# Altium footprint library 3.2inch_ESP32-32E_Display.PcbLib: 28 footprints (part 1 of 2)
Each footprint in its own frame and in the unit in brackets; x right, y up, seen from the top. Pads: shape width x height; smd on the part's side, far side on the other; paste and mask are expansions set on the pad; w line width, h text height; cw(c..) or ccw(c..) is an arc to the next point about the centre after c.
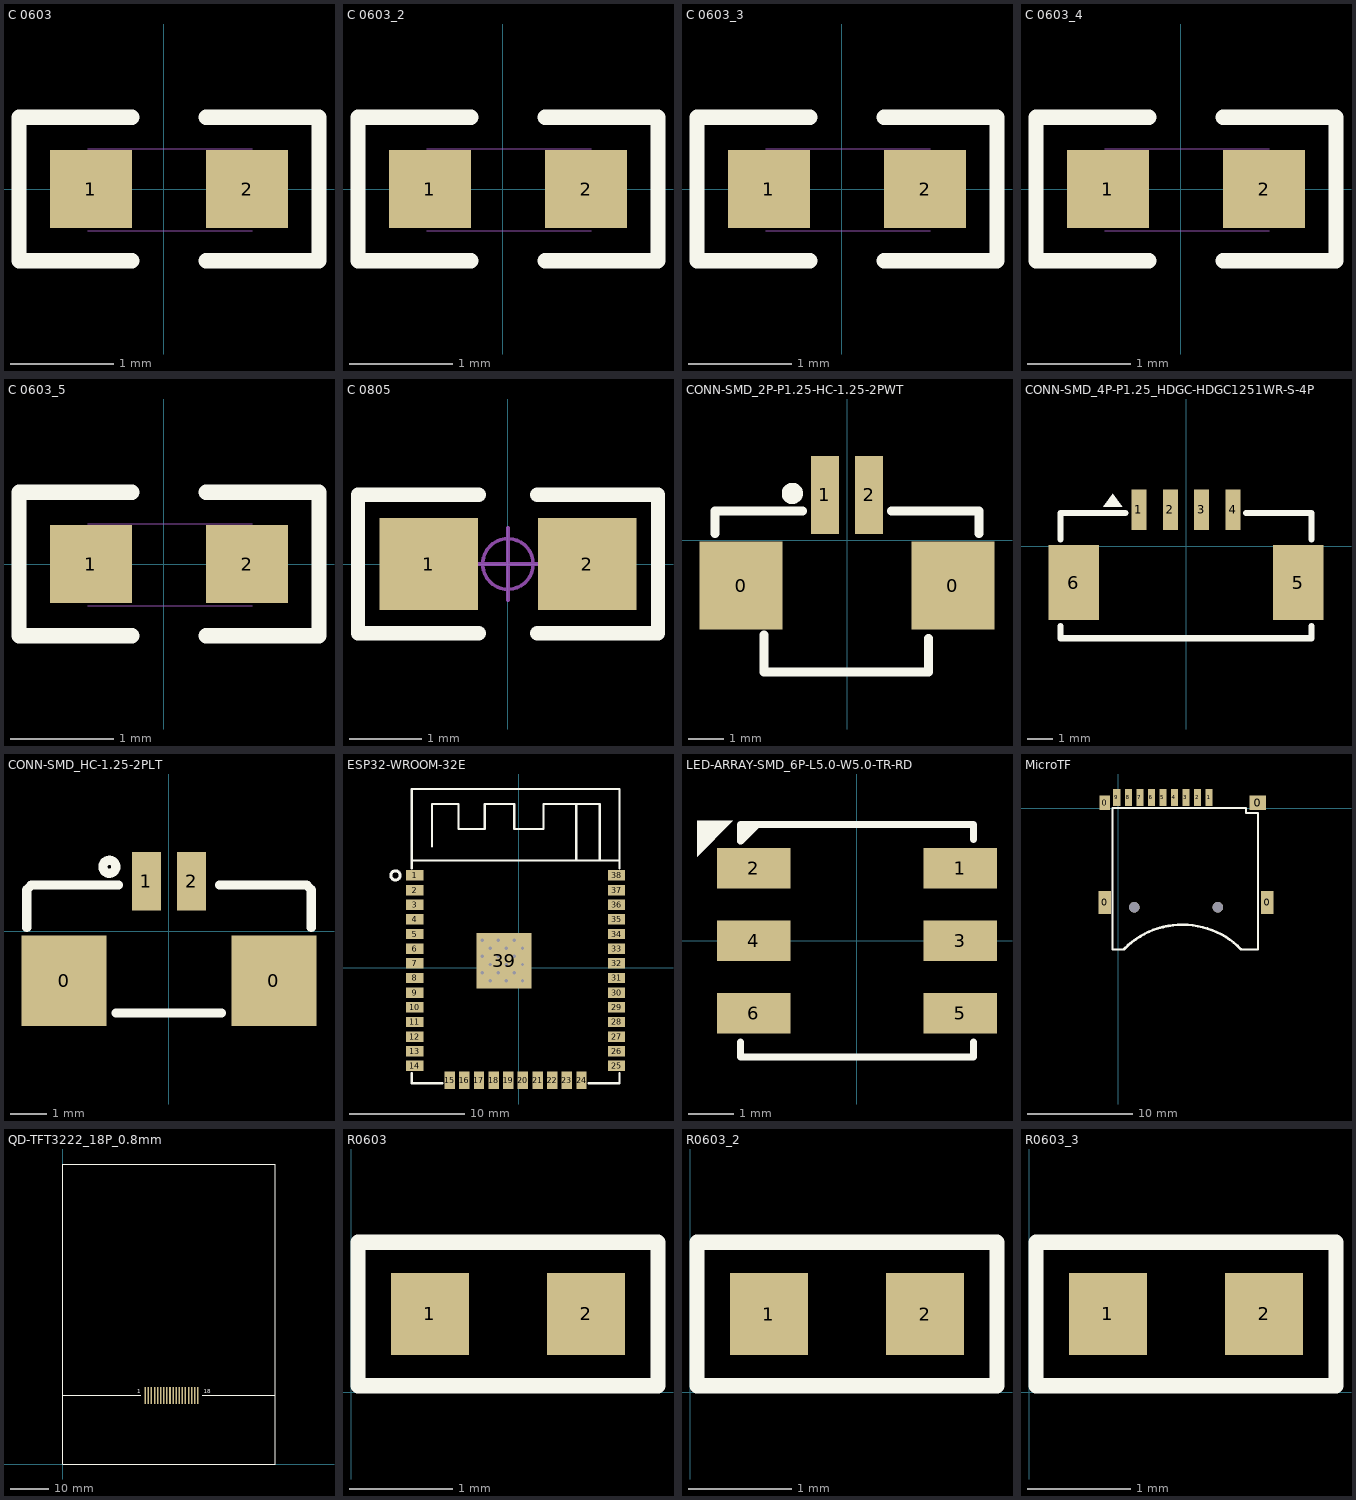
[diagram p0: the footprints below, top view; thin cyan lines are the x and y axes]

## C 0603 [mm] "无极性贴片电容"
pads (2):
  rect 0.8x0.76 smd: 1(-0.711,0) 2(0.809,0)
Top Overlay:
  lines w0.15: -0.311,-0.7 -1.411,-0.7 -1.411,0.7 -0.311,0.7 ; 0.409,-0.7 1.509,-0.7 1.509,0.7 0.409,0.7
Mechanical 13:
  lines w0.01: -0.742,-0.406 0.858,-0.406 ; -0.742,0.394 0.858,0.394
3D body "C 0603.STEP": height 0.81, standoff -0.01, extent -0.742,-0.41 0.858,0.41

## C 0603_2 [mm]
pads (2):
  rect 0.8x0.76 smd: 1(-0.711,0) 2(0.809,0)
Top Overlay:
  lines w0.15: -0.311,-0.7 -1.411,-0.7 -1.411,0.7 -0.311,0.7 ; 0.409,-0.7 1.509,-0.7 1.509,0.7 0.409,0.7
Mechanical 13:
  lines w0.01: -0.742,-0.406 0.858,-0.406 ; -0.742,0.394 0.858,0.394
3D body "C 0603.STEP": height 0.81, standoff -0.01, extent -0.742,-0.41 0.858,0.41

## C 0603_3 [mm]
pads (2):
  rect 0.8x0.76 smd: 1(-0.711,0) 2(0.809,0)
Top Overlay:
  lines w0.15: -0.311,-0.7 -1.411,-0.7 -1.411,0.7 -0.311,0.7 ; 0.409,-0.7 1.509,-0.7 1.509,0.7 0.409,0.7
Mechanical 13:
  lines w0.01: -0.742,-0.406 0.858,-0.406 ; -0.742,0.394 0.858,0.394
3D body "C 0603.STEP": height 0.81, standoff -0.01, extent -0.742,-0.41 0.858,0.41

## C 0603_4 [mm]
pads (2):
  rect 0.8x0.76 smd: 1(-0.711,0) 2(0.809,0)
Top Overlay:
  lines w0.15: -0.311,-0.7 -1.411,-0.7 -1.411,0.7 -0.311,0.7 ; 0.409,-0.7 1.509,-0.7 1.509,0.7 0.409,0.7
Mechanical 13:
  lines w0.01: -0.742,-0.406 0.858,-0.406 ; -0.742,0.394 0.858,0.394
3D body "C 0603.STEP": height 0.81, standoff -0.01, extent -0.742,-0.41 0.858,0.41

## C 0603_5 [mm]
pads (2):
  rect 0.8x0.76 smd: 1(-0.711,0) 2(0.809,0)
Top Overlay:
  lines w0.15: -0.311,-0.7 -1.411,-0.7 -1.411,0.7 -0.311,0.7 ; 0.409,-0.7 1.509,-0.7 1.509,0.7 0.409,0.7
Mechanical 13:
  lines w0.01: -0.742,-0.406 0.858,-0.406 ; -0.742,0.394 0.858,0.394
3D body "C 0603.STEP": height 0.81, standoff -0.01, extent -0.742,-0.41 0.858,0.41

## C 0805 [mm] "无极性贴片电容"
height 0.5
pads (2):
  rect 1.36x1.27 smd: 1(-1.094,0) 2(1.094,0)
Top Overlay:
  lines w0.2: -0.406,-0.955 -2.074,-0.955 -2.074,0.955 -0.406,0.955 ; 0.406,-0.955 2.074,-0.955 ; 0.406,0.955 2.074,0.955 ; 2.075,-0.955 2.075,0.955
Mechanical 15:
  circle w0.05: c0,0 r0.35
  lines w0.05: -0.5,0 0.5,0 ; 0,-0.5 0,0.5
3D body "C 0805.STEP": height 0.51, standoff -0.01, extent -1,-0.61 1,0.61

## CONN-SMD_2P-P1.25-HC-1.25-2PWT [mm]
pads (4):
  rect 2.35x2.5 smd paste+0 mask+0.05: 0(-3.005,-1.285) 0(3.005,-1.285)
  rect 0.8x2.2 smd paste+0 mask+0.05: 1(-0.625,1.285) 2(0.625,1.285)
Top Overlay:
  circle w0.3: c-1.55,1.33 r0.15
  lines w0.254: -3.75,0.196 -3.75,0.835 -1.256,0.835 ; -2.36,-2.69 -2.36,-3.73 2.31,-3.73 2.31,-2.78 ; 1.256,0.835 3.75,0.835 3.75,0.196

## CONN-SMD_4P-P1.25_HDGC-HDGC1251WR-S-4P [mm]
pads (6):
  rect 0.6x1.6 smd mask+0.05: 1(-1.875,1.45) 2(-0.625,1.45) 3(0.625,1.45) 4(1.875,1.45)
  rect 2x3 smd mask+0.05: 5(4.475,-1.45) 6(-4.475,-1.45)
Top Overlay:
  region: -3.175,1.577 -3.302,1.577 -2.921,2.085 -2.54,1.577 -3.175,1.577
  lines w0.254: -5,-3.181 -5,-3.669 5,-3.669 5,-3.181 ; -5,0.281 -5,1.323 -2.413,1.323 ; 2.406,1.323 5,1.323 5,0.281

## CONN-SMD_HC-1.25-2PLT [mm]
pads (4):
  rect 2.35x2.5 smd paste+0 mask+0.05: 0(-2.9,-1.38) 0(2.9,-1.38)
  rect 0.8x1.62 smd paste+0 mask+0.05: 1(-0.625,1.38) 2(0.625,1.38)
Top Overlay:
  circle w0.254: c-1.651,1.778 r0.18
  lines w0.254: -3.937,0.101 -3.937,1.143 -3.81,1.27 -1.397,1.27 ; -1.47,-2.27 1.451,-2.27 ; 1.397,1.27 3.81,1.27 3.937,1.143 3.937,0.101

## ESP32-WROOM-32E [mm]
pads (39):
  rect 1.5x0.9 smd mask+0.051: 1(-9.004,7.987) 2(-9.004,6.717) 3(-9.004,5.447) 4(-9.004,4.177) 5(-9.004,2.907) 6(-9.004,1.637) 7(-9.004,0.367) 8(-9.004,-0.903) 9(-9.004,-2.173) 10(-9.004,-3.443) 11(-9.004,-4.713) 12(-9.004,-5.983) 13(-9.004,-7.253) 14(-9.004,-8.523) 25(8.496,-8.523) 26(8.496,-7.253) 27(8.496,-5.983) 28(8.496,-4.713) 29(8.496,-3.443) 30(8.496,-2.173) 31(8.496,-0.903) 32(8.496,0.367) 33(8.496,1.637) 34(8.496,2.907) 35(8.496,4.177) 36(8.496,5.447) 37(8.496,6.717) 38(8.496,7.987)
  rect 0.9x1.5 smd mask+0.051: 15(-5.969,-9.774) 16(-4.699,-9.774) 17(-3.429,-9.774) 18(-2.159,-9.774) 19(-0.889,-9.774) 20(0.381,-9.774) 21(1.651,-9.774) 22(2.921,-9.774) 23(4.191,-9.774) 24(5.461,-9.774)
  rect 4.8x4.8 smd mask+0.051: 39(-1.254,0.576)
via -1.054,-1.133 diameter 0.5 hole 0.3
via -2.454,-1.133 diameter 0.5 hole 0.3
via -2.454,0.267 diameter 0.5 hole 0.3
via -1.054,0.267 diameter 0.5 hole 0.3
via -1.054,1.667 diameter 0.5 hole 0.3
via -0.354,0.967 diameter 0.5 hole 0.3
via -0.354,-0.433 diameter 0.5 hole 0.3
via -3.154,-0.433 diameter 0.5 hole 0.3
via -3.154,0.967 diameter 0.5 hole 0.3
via -2.454,1.667 diameter 0.5 hole 0.3
via -1.754,-0.433 diameter 0.5 hole 0.3
via -1.754,0.967 diameter 0.5 hole 0.3
via -1.754,2.367 diameter 0.5 hole 0.3
via -0.354,2.367 diameter 0.5 hole 0.3
via 0.346,1.667 diameter 0.5 hole 0.3
via 0.346,0.267 diameter 0.5 hole 0.3
via -3.154,2.367 diameter 0.5 hole 0.3
via 0.346,-1.133 diameter 0.5 hole 0.3
Top Overlay:
  circle w0.254: c-10.668,7.986 r0.402
  lines w0.203: -9.254,-9.15 -9.254,-10.023 -6.596,-10.023 ; -9.254,8.613 -9.254,15.476 8.746,15.477 8.746,8.614 ; -9.254,9.287 8.746,9.287 ; -7.493,10.489 -7.493,14.172 -5.207,14.172 -5.207,12.013 -2.921,12.013 -2.921,14.172 -0.381,14.172 -0.381,12.013 2.159,12.013 2.159,14.172 5.011,14.172 5.011,9.287 ; 4.808,14.172 7.043,14.172 7.043,9.287 ; 6.088,-10.023 8.746,-10.023 8.746,-9.15
3D body "ESP32-WROOM-32E_20210903.STEP": height 3.2, standoff 0.1, extent -9.254,-10.023 8.746,15.477

## LED-ARRAY-SMD_6P-L5.0-W5.0-TR-RD [mm]
pads (6):
  rect 1.625x0.896 smd mask+0.051: 1(2.288,1.6) 2(-2.288,1.6) 3(2.288,0) 4(-2.288,0) 5(2.288,-1.6) 6(-2.288,-1.6)
Top Overlay:
  region: -2.874,2.652 -3.54,2.652 -3.54,1.859 -2.747,2.652
  region: -2.54,2.159 -2.54,2.202 -2.576,2.239
  region: -2.286,2.576 -2.576,2.576 -2.576,2.239 -2.497,2.239 -2.159,2.576
  lines w0.152: -2.576,-2.239 -2.576,-2.576 2.576,-2.576 2.576,-2.239 ; -2.202,2.576 -2.576,2.202 -2.576,2.576 2.576,2.576 2.576,2.239

## MicroTF [mm]
height 2.65
pads (15):
  rect 1x1.4 smd: 0(-1.3,0.526)
  rect 1.2x2.2 smd: 0(-1.3,-8.994) 0(14.2,-8.994)
  rect 1.6x1.4 smd: 0(13.3,0.526)
  rect 0.7x1.6 smd: 1(8.65,1.026) 2(7.55,1.026) 3(6.45,1.026) 4(5.35,1.026) 5(4.25,1.026) 6(3.15,1.026) 7(2.05,1.026) 8(0.95,1.026) 9(-0.15,1.026)
  round 1 hole 1 unplated: ""(1.52,-9.474) ""(9.5,-9.474)
Top Overlay:
  lines w0.2: 0.563,-13.5 -0.559,-13.5 -0.559,0.026 12.192,0.026 ; 11.709,-13.5 13.335,-13.5 13.335,-0.483
  lines w0.203: 12.192,0.026 12.192,-0.483 13.335,-0.483
  lines w0.254: 0.563,-13.43 cw(c6.113,-18.98) 11.721,-13.489
3D body "User Library-MEM2055-00-190-01-A_revG.STEP": height 1.85, standoff -0.6, extent -1.548,-13.472 14.452,1.778

## QD-TFT3222_18P_0.8mm [mm] "3.2inch TFT IPS"
pads (18):
  rect 0.4x4.5 smd: 1(21.38,17.76) 2(22.18,17.76) 3(22.98,17.76) 4(23.78,17.76) 5(24.58,17.76) 6(25.38,17.76) 7(26.18,17.76) 8(26.98,17.76) 9(27.78,17.76) 10(28.58,17.76) 11(29.38,17.76) 12(30.18,17.76) 13(30.98,17.76) 14(31.78,17.76) 15(32.58,17.76) 16(33.38,17.76) 17(34.18,17.76) 18(34.98,17.76)
Top Overlay:
  lines w0.254: 0,17.76 20.239,17.76 ; 0,77.7 0,0 55.04,0 ; 0,77.709 55.04,77.709 55.04,0.009 ; 36.068,17.76 55.04,17.76
  text "1" at 19.304,18.288 h1.02
  text "18" at 36.576,18.288 h1.02

## R0603 [mm]
pads (2):
  rect 0.76x0.8 smd: 1(0.766,0.762) 2(2.286,0.762)
Top Overlay:
  lines w0.15: 0.066,0.062 0.066,1.462 2.986,1.462 2.986,0.062 0.066,0.062
3D body "RES0603.STEP": height 0.65, standoff 0.2, extent 0.749,0.348 2.349,1.168

## R0603_2 [mm]
pads (2):
  rect 0.76x0.8 smd: 1(0.766,0.762) 2(2.286,0.762)
Top Overlay:
  lines w0.15: 0.066,0.062 2.986,0.062 2.986,1.462 0.066,1.462 0.066,0.062
3D body "RES0603.STEP": height 0.65, standoff 0.2, extent 0.749,0.348 2.349,1.168

## R0603_3 [mm]
pads (2):
  rect 0.76x0.8 smd: 1(0.766,0.762) 2(2.286,0.762)
Top Overlay:
  lines w0.15: 0.066,0.062 0.066,1.462 2.986,1.462 2.986,0.062 0.066,0.062
3D body "RES0603.STEP": height 0.65, standoff 0.2, extent 0.749,0.348 2.349,1.168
